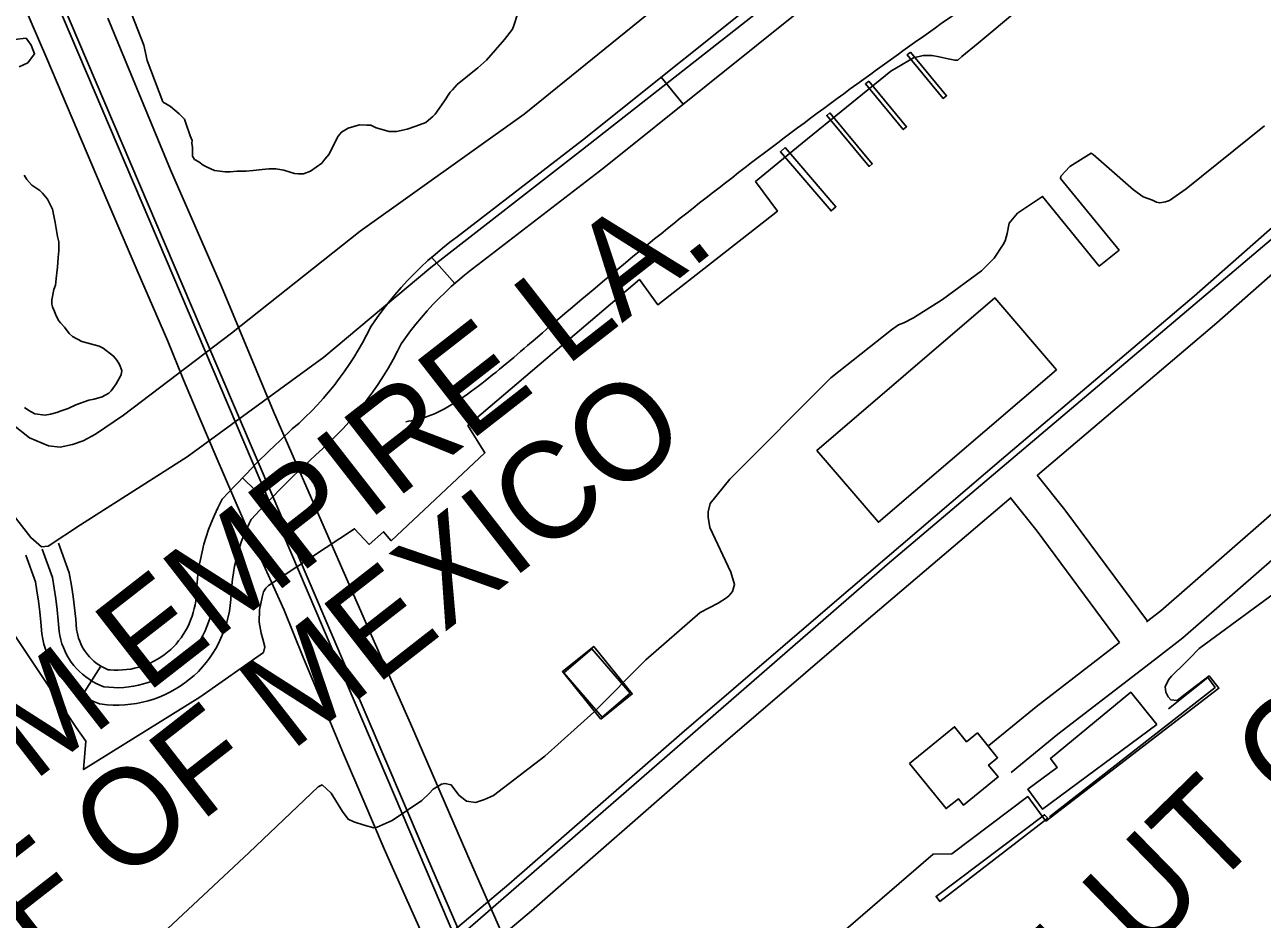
# Model space of a CAD drawing. Extents: x 3812694 to 3850888, y 319753 to 345638.
# Drawn here: x 3831459 to 3832522, y 326034 to 326802 of the extents above; entities that cross this region are included whole.
import ezdxf

# ---------------------------------------------------------------- set-up
doc = ezdxf.new("R2010")
doc.units = 0
for name, color, linetype in [('V-BLDG-OTLN', 7, 'Continuous'), ('V-BRDG-OTLN', 7, 'Continuous'), ('V-CHAN-DOCK', 7, 'Continuous'), ('V-LEVE-TOET', 7, 'Continuous'), ('V-RIVR-IDEN', 7, 'Continuous'), ('V-ROAD-CNTR', 7, 'Continuous'), ('V-RRAP-FSHR', 7, 'Continuous'), ('V-SITE-VEGE', 7, 'Continuous'), ('V-TOPO-SHOR', 7, 'Continuous')]:
    doc.layers.add(name, color=color, linetype=linetype)

msp = doc.modelspace()

# ---------------------------------------------------------------- linework, layer by layer
at = {"layer": 'V-BLDG-OTLN'}
for points in [[(3832345.2, 326506.1), (3832192.3, 326375), (3832139.5, 326436.6), (3832292.4, 326567.7)], [(3831946.2, 326266.4), (3831979, 326228.3), (3831954.9, 326207.6), (3831922.2, 326245.7)], [(3832431.5, 326201.4), (3832333.4, 326128.5), (3832320.7, 326145.6), (3832346, 326164.4), (3832340.3, 326172.1), (3832409.1, 326229)], [(3832219, 326167.9), (3832257.8, 326199.3), (3832268.1, 326186.5), (3832277.4, 326194), (3832294.7, 326172.7), (3832287, 326166.4), (3832295.3, 326156.2), (3832265.4, 326132), (3832261, 326137.5), (3832250.5, 326129)]]:
    msp.add_lwpolyline(points, close=True, dxfattribs=at)
at = {"layer": 'V-BRDG-OTLN'}
for p, q in [((3831477.9, 326773.5), (3831458, 326819.2)), ((3831530.2, 326808.2), (3831584.2, 326677.7)), ((3831503.6, 326712.7), (3831477.9, 326773.5)), ((3831529.5, 326652), (3831503.6, 326712.7)), ((3831584.2, 326677.7), (3831627.8, 326577.7)), ((3831555.5, 326591.3), (3831529.5, 326652)), ((3831581.8, 326530.7), (3831555.5, 326591.3)), ((3831627.8, 326577.7), (3831672.7, 326470.1)), ((3831595.4, 326497.4), (3831581.8, 326530.7)), ((3831609.3, 326464.3), (3831595.4, 326497.4)), ((3831672.7, 326470.1), (3831722.3, 326356.7)), ((3831623.4, 326431.2), (3831609.3, 326464.3)), ((3831637.7, 326398.1), (3831623.4, 326431.2)), ((3831652.1, 326365.2), (3831637.7, 326398.1)), ((3831666.8, 326332.4), (3831652.1, 326365.2)), ((3831722.3, 326356.7), (3831755.7, 326280.2)), ((3831681.7, 326299.6), (3831666.8, 326332.4)), ((3831698.5, 326258.4), (3831681.7, 326299.6)), ((3831755.7, 326280.2), (3831790.2, 326202.1)), ((3831715.5, 326217.3), (3831698.5, 326258.4)), ((3831732.7, 326176.2), (3831715.5, 326217.3)), ((3831790.2, 326202.1), (3831841.7, 326083.9)), ((3831750.2, 326135.3), (3831732.7, 326176.2)), ((3831767.8, 326094.4), (3831750.2, 326135.3)), ((3831786.4, 326052.7), (3831767.8, 326094.4)), ((3831841.7, 326083.9), (3831888.9, 325976.3)), ((3831804.9, 326011), (3831786.4, 326052.7))]:
    msp.add_line(p, q, dxfattribs=at)
msp.add_lwpolyline([(3831236, 327422.7), (3831370.1, 327104.6), (3831609.5, 326543.2), (3831800.4, 326097), (3832029.2, 325568.9), (3832098.1, 325407.9)], dxfattribs=at)
at = {"layer": 'V-CHAN-DOCK'}
for points in [[(3832219.8, 326778.9), (3832250.9, 326741.5), (3832248.1, 326739.2), (3832217, 326776.6), (3832219.8, 326778.9)], [(3832184.1, 326754), (3832216.5, 326714.8), (3832213.6, 326712.4), (3832181.2, 326751.6), (3832184.1, 326754)], [(3832150.6, 326726.8), (3832187, 326682.9), (3832184.3, 326680.7), (3832147.9, 326724.6), (3832150.6, 326726.8)], [(3832112.2, 326697), (3832155.8, 326646.1), (3832151.6, 326642.5), (3832108.1, 326693.4), (3832112.2, 326697)], [(3831953.9, 326205.8), (3831920.9, 326246.8), (3831947.8, 326268.4), (3831980.8, 326227.5), (3831953.9, 326205.8)], [(3832337.9, 326120.7), (3832245.2, 326049.2), (3832241.9, 326053.5), (3832335.1, 326123.8), (3832337.9, 326120.7)]]:
    msp.add_lwpolyline(points, dxfattribs=at)
at = {"layer": 'V-LEVE-TOET'}
for points in [[(3832535.9, 327153), (3832509.7, 327171.6), (3832493.5, 327177.7), (3832480.4, 327179.2), (3832469.4, 327176.7), (3832451.8, 327166.3), (3832359.1, 327093.5), (3832254.7, 327014.3), (3832201.4, 326980.9), (3832136.1, 326930.5), (3832016.1, 326829.5), (3831887.9, 326725.5), (3831747, 326625), (3831636.4, 326537.4), (3831543.7, 326467), (3831519.8, 326450.6), (3831509.2, 326445), (3831499.8, 326441.7), (3831489.2, 326439.6), (3831479.3, 326440.7), (3831463, 326447.6), (3831447.9, 326459.7)], [(3831440.9, 326391.6), (3831464.1, 326361.9), (3831473.2, 326353.8), (3831479.1, 326354.6), (3831506.9, 326372.7), (3831598.5, 326431.3), (3831715.9, 326516.9), (3831807.7, 326594), (3831938, 326695.2), (3832139.7, 326853.6), (3832302.8, 326980.8), (3832432.6, 327087.9), (3832465.8, 327110.7), (3832476.8, 327116), (3832487.5, 327115.3), (3832497.4, 327109.9), (3832506.9, 327102.1), (3832536, 327076)]]:
    msp.add_lwpolyline(points, dxfattribs=at)
at = {"layer": 'V-ROAD-CNTR'}
for p, q in [((3832005.7, 326757.5), (3832024.5, 326734.1)), ((3831808.5, 326602.7), (3831828.4, 326580.2)), ((3831645.9, 326413.2), (3831667.5, 326392.4)), ((3831524.2, 326251.5), (3831508.3, 326226.1))]:
    msp.add_line(p, q, dxfattribs=at)
for points in [[(3832088.4, 325411.4), (3831857.4, 325950.7), (3831227.4, 327429.2)], [(3831488, 326357), (3831497.2, 326331.6), (3831499, 326320.8), (3831500.5, 326311.2), (3831501.7, 326301.5), (3831502.7, 326291.8), (3831503.4, 326283), (3831503.8, 326280.6), (3831504.4, 326278), (3831505.2, 326275.4), (3831506.1, 326272.9), (3831507.1, 326270.5), (3831508.3, 326268.1), (3831509.7, 326265.8), (3831511.1, 326263.6), (3831512.7, 326261.5), (3831514.5, 326259.5), (3831516.3, 326257.6), (3831518.3, 326255.8), (3831520.4, 326254.1), (3831522.5, 326252.6), (3831524.8, 326251.1), (3831527.1, 326249.9), (3831529.5, 326248.7), (3831530.5, 326248.3), (3831532.3, 326248.1), (3831535.8, 326247.9), (3831539.3, 326247.9), (3831542.9, 326248.1), (3831546.4, 326248.4), (3831549.9, 326248.9), (3831553.3, 326249.6), (3831556.8, 326250.5), (3831560.1, 326251.5), (3831563.4, 326252.8), (3831566.7, 326254.1), (3831569.8, 326255.7), (3831572.9, 326257.4), (3831575.9, 326259.2), (3831578.8, 326261.2), (3831581.6, 326263.4), (3831584.3, 326265.7), (3831586.7, 326268), (3831588.9, 326270.4), (3831591.1, 326273.1), (3831593.2, 326275.8), (3831595.1, 326278.7), (3831596.9, 326281.6), (3831598.6, 326284.7), (3831600.1, 326287.8), (3831601.4, 326290.9), (3831602.6, 326294.2), (3831603.7, 326297.5), (3831604.5, 326300.8), (3831605.2, 326304.2), (3831605.8, 326307.6), (3831606.1, 326310.8), (3831606.4, 326316.7), (3831606.9, 326323.3), (3831607.6, 326330), (3831608.5, 326336.6), (3831609.8, 326343.1), (3831611.2, 326349.6), (3831612.9, 326356.1), (3831614.8, 326362.5), (3831616.9, 326368.8), (3831619.3, 326375.1), (3831621.9, 326381.2), (3831624.7, 326387.3), (3831628.6, 326394.9), (3831639.4, 326406.4), (3831649, 326416.4), (3831658.7, 326426.3), (3831668.6, 326436), (3831678.5, 326445.6), (3831688.7, 326455.2), (3831694.6, 326460.3), (3831699.9, 326465.4), (3831705.2, 326470.5), (3831710.3, 326475.9), (3831715.2, 326481.3), (3831720, 326486.9), (3831724.6, 326492.6), (3831729.1, 326498.4), (3831733.4, 326504.4), (3831737.6, 326510.5), (3831741.6, 326516.6), (3831745.4, 326522.9), (3831749.1, 326529.3), (3831752.5, 326535.8), (3831756.4, 326543.6), (3831761.6, 326551), (3831766.5, 326557.6), (3831771.6, 326564.1), (3831776.8, 326570.4), (3831782.2, 326576.6), (3831787.7, 326582.6), (3831793.4, 326588.5), (3831799.3, 326594.2), (3831805.3, 326599.8), (3831811.4, 326605.2), (3831817.7, 326610.5), (3831824.1, 326615.6), (3831830.5, 326620.3), (3831938, 326703.2), (3832113.7, 326843.9)], [(3831459.8, 326346.7), (3831468.1, 326323.9), (3831469.4, 326316.1), (3831470.7, 326307.1), (3831471.9, 326298.1), (3831472.8, 326289.1), (3831473.6, 326279.2), (3831474.4, 326274.6), (3831475.4, 326270.3), (3831476.7, 326266), (3831478.2, 326261.8), (3831480, 326257.7), (3831482, 326253.7), (3831484.2, 326249.9), (3831486.7, 326246.2), (3831489.4, 326242.6), (3831492.3, 326239.3), (3831495.4, 326236), (3831498.7, 326233), (3831502.2, 326230.2), (3831505.8, 326227.6), (3831509.6, 326225.3), (3831513.5, 326223.1), (3831517.5, 326221.2), (3831523.2, 326219), (3831529.8, 326218.2), (3831534.9, 326218), (3831539.9, 326217.9), (3831545, 326218.2), (3831550, 326218.6), (3831555, 326219.4), (3831560, 326220.4), (3831564.9, 326221.6), (3831569.7, 326223.1), (3831574.4, 326224.8), (3831579.1, 326226.8), (3831583.6, 326229), (3831588.1, 326231.5), (3831592.4, 326234.1), (3831596.5, 326237), (3831600.5, 326240.1), (3831604.4, 326243.4), (3831608.2, 326246.9), (3831611.6, 326250.7), (3831614.7, 326254.5), (3831617.7, 326258.4), (3831620.4, 326262.5), (3831623, 326266.7), (3831625.3, 326271), (3831627.4, 326275.4), (3831629.3, 326279.9), (3831631, 326284.5), (3831632.5, 326289.2), (3831633.7, 326293.9), (3831634.7, 326298.7), (3831635.5, 326303.6), (3831636.1, 326308.6), (3831636.3, 326315), (3831636.7, 326320.6), (3831637.3, 326326.1), (3831638.2, 326331.7), (3831639.2, 326337.2), (3831640.4, 326342.6), (3831641.8, 326348), (3831643.4, 326353.4), (3831645.2, 326358.7), (3831647.1, 326363.9), (3831649.3, 326369.1), (3831651.7, 326374.1), (3831653.4, 326377.5), (3831661.2, 326385.8), (3831670.5, 326395.5), (3831680, 326405.1), (3831689.5, 326414.6), (3831699.2, 326423.9), (3831708.9, 326433), (3831714.7, 326438.2), (3831720.7, 326443.7), (3831726.5, 326449.5), (3831732.2, 326455.4), (3831737.7, 326461.4), (3831743, 326467.6), (3831748.2, 326474), (3831753.2, 326480.5), (3831758, 326487.1), (3831762.6, 326493.8), (3831767, 326500.7), (3831771.3, 326507.7), (3831775.3, 326514.8), (3831779.2, 326522), (3831782.2, 326528.2), (3831786, 326533.5), (3831790.4, 326539.4), (3831795, 326545.3), (3831799.7, 326551), (3831804.5, 326556.6), (3831809.5, 326562), (3831814.7, 326567.4), (3831820, 326572.5), (3831825.4, 326577.6), (3831831, 326582.5), (3831836.7, 326587.2), (3831842.5, 326591.8), (3831848.6, 326596.5), (3831956.5, 326679.6), (3832132.3, 326820.4)], [(3832727.3, 326802.4), (3832624.4, 326710.8), (3832463.6, 326569.2), (3832298.2, 326428.8), (3832154.5, 326306.5), (3832023.3, 326193.9), (3831874.7, 326064.1), (3831756.3, 325964.1), (3831638.7, 325858.8), (3831608.1, 325832.5)], [(3832746, 326779), (3832644.3, 326688.4), (3832483.2, 326546.5), (3832328.9, 326415.5)], [(3832688, 326752.1), (3832199.8, 326338.7), (3831821.9, 326010), (3831501, 325729.9), (3831471.4, 325704.7)], [(3832423.4, 326290), (3832352.5, 326385.8), (3832328.8, 326415.4)], [(3832575.5, 326421.8), (3832434.9, 326299), (3832422.8, 326289.6)], [(3832306.4, 326396.4), (3832174, 326283.7), (3832042.9, 326171.2), (3831894.2, 326041.3), (3831776, 325941.4), (3831658.5, 325836.2), (3831614.8, 325798.7), (3831504.4, 325703.8)], [(3832399.6, 326271.7), (3832328.8, 326367.5), (3832305.9, 326396)], [(3832595.5, 326399.4), (3832454, 326275.8), (3832429.6, 326256.9), (3832346.5, 326192.9), (3832306.3, 326160.1)], [(3831473.9, 326351.8), (3831482.7, 326327.7), (3831484.2, 326318.5), (3831485.6, 326309.2), (3831486.8, 326299.8), (3831487.7, 326290.5), (3831488.5, 326281.1), (3831489.1, 326277.6), (3831489.9, 326274.1), (3831490.9, 326270.7), (3831492.1, 326267.4), (3831493.5, 326264.1), (3831495.1, 326260.9), (3831496.9, 326257.9), (3831498.9, 326254.9), (3831501.1, 326252.1), (3831503.4, 326249.4), (3831505.9, 326246.8), (3831508.5, 326244.4), (3831511.3, 326242.2), (3831514.2, 326240.1), (3831517.2, 326238.2), (3831520.3, 326236.5), (3831523.5, 326235), (3831526.8, 326233.7), (3831531.1, 326233.2), (3831535.4, 326233), (3831539.6, 326232.9), (3831543.9, 326233.1), (3831548.2, 326233.5), (3831552.4, 326234.2), (3831556.7, 326235), (3831560.8, 326236.1), (3831564.9, 326237.3), (3831568.9, 326238.8), (3831572.9, 326240.5), (3831576.7, 326242.4), (3831580.5, 326244.4), (3831584.1, 326246.7), (3831587.7, 326249.1), (3831591.1, 326251.7), (3831594.3, 326254.5), (3831597.5, 326257.5), (3831600.3, 326260.6), (3831602.9, 326263.8), (3831605.4, 326267.1), (3831607.8, 326270.6), (3831609.9, 326274.1), (3831611.9, 326277.8), (3831613.8, 326281.6), (3831615.4, 326285.4), (3831616.8, 326289.3), (3831618.1, 326293.3), (3831619.1, 326297.4)], [(3832399.6, 326271.7), (3832327.9, 326216.4), (3832287.3, 326183.3)]]:
    msp.add_lwpolyline(points, dxfattribs=at)
for points in [[(3832623.9, 326963.7), (3832590.8, 326992.1), (3832563.6, 326995.7), (3832523.2, 326981.5), (3832469.7, 326951.9), (3832301.2, 326841.8), (3832173.9, 326751.5), (3831994.6, 326614), (3831890.9, 326526.9), (3831841.9, 326487), (3831795.4, 326463.1), (3831786.2, 326461.4)], [(3833225.7, 326232.1), (3833214.5, 326190), (3833178.2, 326131.5), (3833127.6, 326072.8), (3833076.8, 326031.8), (3832985.9, 325973.2), (3832863.3, 325890.7), (3832748.1, 325818.3), (3832649.4, 325759.5), (3832576.8, 325725.9), (3832528, 325701.8), (3832489.9, 325679), (3832465, 325655.2)]]:
    msp.add_spline(points, degree=3, dxfattribs=at)
at = {"layer": 'V-RRAP-FSHR'}
msp.add_lwpolyline([(3832441.5, 326214.6), (3832475.3, 326241.7), (3832481.6, 326233.1), (3832339.4, 326121.9)], dxfattribs=at)
at = {"layer": 'V-SITE-VEGE'}
for points in [[(3831698.5, 326674.5), (3831693.9, 326674.4), (3831690.7, 326674.8), (3831687, 326675.7), (3831681.4, 326677.5), (3831674.5, 326678.8), (3831668.5, 326678.8), (3831663, 326678.2), (3831655.2, 326677.2), (3831649.2, 326676.7), (3831641.4, 326676.6), (3831635.4, 326676.1), (3831631.2, 326676), (3831622, 326677.3), (3831615.5, 326680), (3831612.3, 326681.8), (3831608.5, 326684.6), (3831604.8, 326686.8), (3831603, 326689.6), (3831602.9, 326696.9), (3831602.4, 326700.6), (3831602.8, 326702.9), (3831600.9, 326707.1), (3831599.5, 326711.2), (3831598.5, 326714.4), (3831596.2, 326721.3), (3831591.5, 326725.9), (3831584.1, 326732.2), (3831579.9, 326734.9), (3831578, 326735.8), (3831577.4, 326736.3), (3831564.1, 326771.7), (3831561.2, 326784.9), (3831550.9, 326811.3)], [(3831882.3, 326811.5), (3831879.2, 326801.8), (3831877.9, 326798.6), (3831871, 326789.7), (3831855.6, 326772.1), (3831848.3, 326765.5), (3831830.4, 326751), (3831826.4, 326746.4), (3831824.5, 326744.5), (3831819.1, 326736.2), (3831811.4, 326725.5), (3831809.5, 326723.6), (3831807.7, 326722.2), (3831803.6, 326718.5), (3831794.9, 326715.2), (3831787.5, 326712.8), (3831778.3, 326710.8), (3831771.9, 326710.8), (3831760.8, 326713.9), (3831756.2, 326716.1), (3831752.9, 326716.1), (3831746.5, 326716.5), (3831736.8, 326713.6), (3831730.9, 326710.3), (3831728.1, 326706.6), (3831726.3, 326702.9), (3831720.5, 326691.3), (3831716.8, 326687.1), (3831714.1, 326683.4), (3831704.5, 326676.8), (3831698.5, 326674.5)], [(3831450.2, 326789.8), (3831460.1, 326790.8), (3831464.5, 326784.9), (3831467.4, 326777.6), (3831461.5, 326769.6), (3831454.2, 326766.3)], [(3831458.4, 326673.2), (3831460.7, 326669.6), (3831464.9, 326664.6), (3831471.9, 326660), (3831474.2, 326657.7), (3831478.4, 326652.7), (3831482.7, 326644), (3831485.1, 326632.5), (3831487.1, 326620.5), (3831488.1, 326615.9), (3831488.1, 326608.1), (3831487.7, 326602.6), (3831486.9, 326594.3), (3831486.5, 326589.2), (3831486.1, 326586.9), (3831485.2, 326578.6), (3831483.9, 326574.9), (3831482.1, 326566.1), (3831482.2, 326562.4), (3831482.7, 326560.1), (3831484.6, 326556), (3831486, 326552.3), (3831488.3, 326548.2), (3831489.7, 326546.4), (3831493, 326542.7), (3831497.2, 326537.2), (3831500, 326534.5), (3831507.9, 326530.4), (3831522.7, 326526.4), (3831526.4, 326524.6), (3831535.2, 326517.8), (3831538, 326514.2), (3831540.4, 326510.5), (3831542.3, 326505.5), (3831541.8, 326501.8), (3831537.3, 326493.9), (3831533.2, 326487.8), (3831531, 326486), (3831525.5, 326482.7), (3831518.6, 326480.8), (3831514, 326479.8), (3831502.9, 326476), (3831496.1, 326472.7), (3831490.1, 326470.8), (3831486.4, 326469.4), (3831480.9, 326467.9), (3831476.3, 326466.9), (3831467.5, 326468.2), (3831462.4, 326470.9), (3831458.7, 326473.7)]]:
    msp.add_lwpolyline(points, dxfattribs=at)
at = {"layer": 'V-TOPO-SHOR'}
for points in [[(3832347.4, 326844.7), (3832278.1, 326786.5), (3832264, 326775.1), (3832260.5, 326772.1), (3832258.1, 326772), (3832252.2, 326773.2), (3832244.4, 326774.9), (3832238.5, 326776), (3832230.8, 326775.9), (3832222.5, 326774), (3832203.1, 326762.6), (3832126.8, 326700.7), (3832086.8, 326667.7), (3832105.5, 326642.4), (3832002.7, 326561.9), (3831987, 326583.7), (3831839.7, 326458.2), (3831854.2, 326434.7), (3831773.8, 326359.2), (3831767.2, 326366.8), (3831754.9, 326356), (3831742.3, 326369.5), (3831668.2, 326320.7), (3831665.9, 326318.3), (3831664.1, 326315.3), (3831663, 326310.6), (3831660.7, 326299.9), (3831660.3, 326289.2), (3831662.1, 326279.8), (3831663.4, 326274.5), (3831665.2, 326268), (3831664.1, 326263.2), (3831609.4, 326224.7), (3831509.4, 326162.6), (3831511.5, 326186.9)], [(3831774.7, 326118.7), (3831800, 326136.1), (3831806.4, 326142.1), (3831809.9, 326145.7), (3831817, 326149.9), (3831819.9, 326150.6), (3831825.3, 326149.4), (3831831.9, 326140.6), (3831838.5, 326135.4), (3831846.2, 326134.3), (3831853.9, 326136.7), (3831861.5, 326140.3), (3831905.6, 326174), (3831947.8, 326211.8), (3831992.4, 326256.7), (3832039.3, 326297.5), (3832054.6, 326305.4), (3832061.7, 326310.2), (3832064, 326312), (3832067, 326315.6), (3832068.7, 326321.5), (3832065.6, 326332.1), (3832047.4, 326370.5), (3832046.1, 326379.3), (3832046.1, 326384.1), (3832047.8, 326391.2), (3832064.7, 326412.1), (3832151.5, 326499), (3832203.7, 326540.4), (3832209.6, 326544.6), (3832214.3, 326546.4), (3832222.6, 326550.7), (3832247.3, 326566.4), (3832280.8, 326591), (3832291.9, 326601.8), (3832299.5, 326613.7), (3832301.3, 326616.7), (3832303, 326623.2), (3832304.6, 326632.1), (3832311.7, 326640.5), (3832333.4, 326655), (3832382.1, 326595.1), (3832399.1, 326608.9), (3832348.7, 326670.5), (3832349.2, 326672.3), (3832356.8, 326680.7), (3832375.1, 326692.1), (3832376.9, 326691), (3832388.2, 326681), (3832411.6, 326660.6), (3832419.9, 326654.7), (3832427.7, 326651.8), (3832431.2, 326650.1), (3832434.2, 326649.5), (3832438.9, 326650.2), (3832442.5, 326651.4), (3832456.6, 326661.6), (3832524.1, 326715.7)], [(3832569.1, 326340.6), (3832518.5, 326303.9), (3832468, 326266.6), (3832459.8, 326258.2), (3832452.7, 326251), (3832446.9, 326245.6), (3832444, 326242.7), (3832441.6, 326239.7), (3832438.7, 326233.7), (3832439.4, 326229), (3832441.2, 326224.9), (3832443.6, 326222.5), (3832448.9, 326222), (3832456, 326227.4), (3832476.5, 326243), (3832484.9, 326232.4), (3832419.1, 326182), (3832336.3, 326118.3), (3832320.7, 326139.4), (3832255.4, 326090.1), (3832239.5, 326090), (3832149.7, 326012.6)], [(3831511.5, 326186.9), (3831503.1, 326198.7), (3831426, 326313.9)], [(3831445.8, 325912.5), (3831523.3, 325968.4), (3831543.3, 325981.7), (3831546.3, 325981.1), (3831561.3, 325967.7), (3831563.6, 325968.9), (3831571.3, 325975.5), (3831588.2, 325996.4), (3831592.9, 326004.7), (3831577.3, 326021.7), (3831651.8, 326091.3), (3831711, 326147.6), (3831714.5, 326149.4), (3831722.3, 326142.4), (3831731.9, 326126.5), (3831736.7, 326120), (3831741.5, 326117.7), (3831750.4, 326114.9), (3831758.7, 326112.6), (3831761.7, 326113.2), (3831774.7, 326118.7)]]:
    msp.add_lwpolyline(points, dxfattribs=at)

# ---------------------------------------------------------------- texts
at = {"layer": 'V-RIVR-IDEN'}
for s, rotation, p in [('WATERWAY FROM EMPIRE LA.', 37.948, (3830741.7, 325586.5)), ('TO THE GULF OF MEXICO', 37.948, (3830938.5, 325593.3)), ('DOULLUT CANAL ', 44.3251, (3832154.6, 325741.9))]:
    msp.add_text(s, height=83, rotation=rotation, dxfattribs=at).set_placement(p)

doc.saveas('drawing.dxf')
